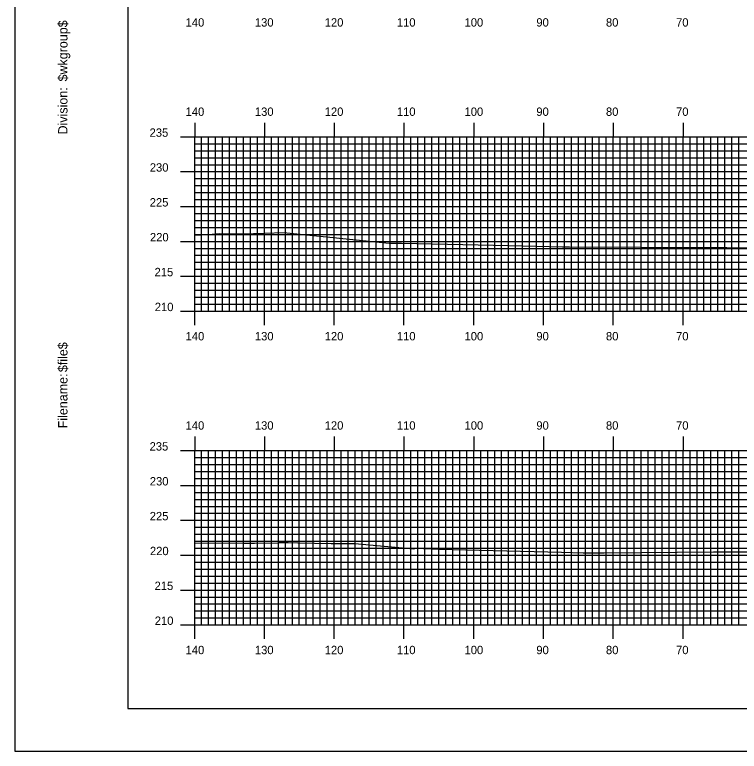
# Model space of a CAD drawing. Extents: x 1804290 to 1804634, y 442591 to 442811.
# Drawn here: x 1804290.4 to 1804394.2, y 442590.5 to 442696.2 of the extents above; entities that cross this region are included whole.
import ezdxf

# ---------------------------------------------------------------- set-up
doc = ezdxf.new("R2010")
doc.units = 0
for name, color, linetype in [('BORDER', 7, 'Continuous'), ('H_V ANNOTATION', 7, 'Continuous'), ('MAJOR', 7, 'Continuous'), ('MINOR', 7, 'Continuous'), ('PLOT BOUNDARY', 7, 'Continuous'), ('S_Roadway_Centerline', 7, 'Continuous')]:
    doc.layers.add(name, color=color, linetype=linetype)

msp = doc.modelspace()

# ---------------------------------------------------------------- linework, layer by layer
at = {"layer": 'BORDER'}
msp.add_lwpolyline([(1804306.57, 442596.67), (1804626.57, 442596.67), (1804626.57, 442806.67), (1804306.57, 442806.67)], close=True, dxfattribs=at)
at = {"layer": 'MAJOR'}
for p, q in [((1804316.17, 442680.67), (1804316.17, 442678.67)), ((1804326.17, 442680.67), (1804326.17, 442678.67)), ((1804336.17, 442680.67), (1804336.17, 442678.67)), ((1804346.17, 442680.67), (1804346.17, 442678.67)), ((1804356.17, 442680.67), (1804356.17, 442678.67)), ((1804366.17, 442680.67), (1804366.17, 442678.67)), ((1804376.17, 442680.67), (1804376.17, 442678.67)), ((1804386.17, 442680.67), (1804386.17, 442678.67)), ((1804314.16, 442678.67), (1804316.17, 442678.67)), ((1804316.17, 442678.67), (1804596.17, 442678.67)), ((1804316.17, 442653.67), (1804316.17, 442678.67)), ((1804316.17, 442653.67), (1804316.17, 442678.67)), ((1804316.17, 442678.67), (1804596.17, 442678.67)), ((1804326.17, 442653.67), (1804326.17, 442678.67)), ((1804336.17, 442653.67), (1804336.17, 442678.67)), ((1804346.17, 442653.67), (1804346.17, 442678.67)), ((1804356.17, 442653.67), (1804356.17, 442678.67)), ((1804366.17, 442653.67), (1804366.17, 442678.67)), ((1804376.17, 442653.67), (1804376.17, 442678.67)), ((1804386.17, 442653.67), (1804386.17, 442678.67)), ((1804314.16, 442673.67), (1804316.17, 442673.67)), ((1804316.17, 442673.67), (1804596.17, 442673.67)), ((1804314.16, 442668.67), (1804316.17, 442668.67)), ((1804316.17, 442668.67), (1804596.17, 442668.67)), ((1804314.16, 442663.67), (1804316.17, 442663.67)), ((1804316.17, 442663.67), (1804596.17, 442663.67)), ((1804314.16, 442658.67), (1804316.17, 442658.67)), ((1804316.17, 442658.67), (1804596.17, 442658.67)), ((1804314.16, 442653.67), (1804316.17, 442653.67)), ((1804316.17, 442653.67), (1804596.17, 442653.67)), ((1804316.17, 442653.67), (1804596.17, 442653.67)), ((1804316.17, 442651.66), (1804316.17, 442653.67)), ((1804326.17, 442651.66), (1804326.17, 442653.67)), ((1804336.17, 442651.66), (1804336.17, 442653.67)), ((1804346.17, 442651.66), (1804346.17, 442653.67)), ((1804356.17, 442651.66), (1804356.17, 442653.67)), ((1804366.17, 442651.66), (1804366.17, 442653.67)), ((1804376.17, 442651.66), (1804376.17, 442653.67)), ((1804386.17, 442651.66), (1804386.17, 442653.67)), ((1804316.17, 442635.67), (1804316.17, 442633.67)), ((1804326.17, 442635.67), (1804326.17, 442633.67)), ((1804336.17, 442635.67), (1804336.17, 442633.67)), ((1804346.17, 442635.67), (1804346.17, 442633.67)), ((1804356.17, 442635.67), (1804356.17, 442633.67)), ((1804366.17, 442635.67), (1804366.17, 442633.67)), ((1804376.17, 442635.67), (1804376.17, 442633.67)), ((1804386.17, 442635.67), (1804386.17, 442633.67)), ((1804314.16, 442633.67), (1804316.17, 442633.67)), ((1804316.17, 442633.67), (1804596.17, 442633.67)), ((1804316.17, 442608.67), (1804316.17, 442633.67)), ((1804316.17, 442608.67), (1804316.17, 442633.67)), ((1804316.17, 442633.67), (1804596.17, 442633.67)), ((1804326.17, 442608.67), (1804326.17, 442633.67)), ((1804336.17, 442608.67), (1804336.17, 442633.67)), ((1804346.17, 442608.67), (1804346.17, 442633.67)), ((1804356.17, 442608.67), (1804356.17, 442633.67)), ((1804366.17, 442608.67), (1804366.17, 442633.67)), ((1804376.17, 442608.67), (1804376.17, 442633.67)), ((1804386.17, 442608.67), (1804386.17, 442633.67)), ((1804314.16, 442628.67), (1804316.17, 442628.67)), ((1804316.17, 442628.67), (1804596.17, 442628.67)), ((1804314.16, 442623.67), (1804316.17, 442623.67)), ((1804316.17, 442623.67), (1804596.17, 442623.67)), ((1804314.16, 442618.67), (1804316.17, 442618.67)), ((1804316.17, 442618.67), (1804596.17, 442618.67)), ((1804314.16, 442613.67), (1804316.17, 442613.67)), ((1804316.17, 442613.67), (1804596.17, 442613.67)), ((1804314.16, 442608.67), (1804316.17, 442608.67)), ((1804316.17, 442608.67), (1804596.17, 442608.67)), ((1804316.17, 442608.67), (1804596.17, 442608.67)), ((1804316.17, 442606.66), (1804316.17, 442608.67)), ((1804326.17, 442606.66), (1804326.17, 442608.67)), ((1804336.17, 442606.66), (1804336.17, 442608.67)), ((1804346.17, 442606.66), (1804346.17, 442608.67)), ((1804356.17, 442606.66), (1804356.17, 442608.67)), ((1804366.17, 442606.66), (1804366.17, 442608.67)), ((1804376.17, 442606.66), (1804376.17, 442608.67)), ((1804386.17, 442606.66), (1804386.17, 442608.67))]:
    msp.add_line(p, q, dxfattribs=at)
at = {"layer": 'MINOR'}
for p, q in [((1804317.17, 442653.67), (1804317.17, 442678.67)), ((1804318.17, 442653.67), (1804318.17, 442678.67)), ((1804319.17, 442653.67), (1804319.17, 442678.67)), ((1804320.17, 442653.67), (1804320.17, 442678.67)), ((1804321.17, 442653.67), (1804321.17, 442678.67)), ((1804322.17, 442653.67), (1804322.17, 442678.67)), ((1804323.17, 442653.67), (1804323.17, 442678.67)), ((1804324.17, 442653.67), (1804324.17, 442678.67)), ((1804325.17, 442653.67), (1804325.17, 442678.67)), ((1804327.17, 442653.67), (1804327.17, 442678.67)), ((1804328.17, 442653.67), (1804328.17, 442678.67)), ((1804329.17, 442653.67), (1804329.17, 442678.67)), ((1804330.17, 442653.67), (1804330.17, 442678.67)), ((1804331.17, 442653.67), (1804331.17, 442678.67)), ((1804332.17, 442653.67), (1804332.17, 442678.67)), ((1804333.17, 442653.67), (1804333.17, 442678.67)), ((1804334.17, 442653.67), (1804334.17, 442678.67)), ((1804335.17, 442653.67), (1804335.17, 442678.67)), ((1804337.17, 442653.67), (1804337.17, 442678.67)), ((1804338.17, 442653.67), (1804338.17, 442678.67)), ((1804339.17, 442653.67), (1804339.17, 442678.67)), ((1804340.17, 442653.67), (1804340.17, 442678.67)), ((1804341.17, 442653.67), (1804341.17, 442678.67)), ((1804342.17, 442653.67), (1804342.17, 442678.67)), ((1804343.17, 442653.67), (1804343.17, 442678.67)), ((1804344.17, 442653.67), (1804344.17, 442678.67)), ((1804345.17, 442653.67), (1804345.17, 442678.67)), ((1804347.17, 442653.67), (1804347.17, 442678.67)), ((1804348.17, 442653.67), (1804348.17, 442678.67)), ((1804349.17, 442653.67), (1804349.17, 442678.67)), ((1804350.17, 442653.67), (1804350.17, 442678.67)), ((1804351.17, 442653.67), (1804351.17, 442678.67)), ((1804352.17, 442653.67), (1804352.17, 442678.67)), ((1804353.17, 442653.67), (1804353.17, 442678.67)), ((1804354.17, 442653.67), (1804354.17, 442678.67)), ((1804355.17, 442653.67), (1804355.17, 442678.67)), ((1804357.17, 442653.67), (1804357.17, 442678.67)), ((1804358.17, 442653.67), (1804358.17, 442678.67)), ((1804359.17, 442653.67), (1804359.17, 442678.67)), ((1804360.17, 442653.67), (1804360.17, 442678.67)), ((1804361.17, 442653.67), (1804361.17, 442678.67)), ((1804362.17, 442653.67), (1804362.17, 442678.67)), ((1804363.17, 442653.67), (1804363.17, 442678.67)), ((1804364.17, 442653.67), (1804364.17, 442678.67)), ((1804365.17, 442653.67), (1804365.17, 442678.67)), ((1804367.17, 442653.67), (1804367.17, 442678.67)), ((1804368.17, 442653.67), (1804368.17, 442678.67)), ((1804369.17, 442653.67), (1804369.17, 442678.67)), ((1804370.17, 442653.67), (1804370.17, 442678.67)), ((1804371.17, 442653.67), (1804371.17, 442678.67)), ((1804372.17, 442653.67), (1804372.17, 442678.67)), ((1804373.17, 442653.67), (1804373.17, 442678.67)), ((1804374.17, 442653.67), (1804374.17, 442678.67)), ((1804375.17, 442653.67), (1804375.17, 442678.67)), ((1804377.17, 442653.67), (1804377.17, 442678.67)), ((1804378.17, 442653.67), (1804378.17, 442678.67)), ((1804379.17, 442653.67), (1804379.17, 442678.67)), ((1804380.17, 442653.67), (1804380.17, 442678.67)), ((1804381.17, 442653.67), (1804381.17, 442678.67)), ((1804382.17, 442653.67), (1804382.17, 442678.67)), ((1804383.17, 442653.67), (1804383.17, 442678.67)), ((1804384.17, 442653.67), (1804384.17, 442678.67)), ((1804385.17, 442653.67), (1804385.17, 442678.67)), ((1804387.17, 442653.67), (1804387.17, 442678.67)), ((1804388.17, 442653.67), (1804388.17, 442678.67)), ((1804389.17, 442653.67), (1804389.17, 442678.67)), ((1804390.17, 442653.67), (1804390.17, 442678.67)), ((1804391.17, 442653.67), (1804391.17, 442678.67)), ((1804392.17, 442653.67), (1804392.17, 442678.67)), ((1804393.17, 442653.67), (1804393.17, 442678.67)), ((1804394.17, 442653.67), (1804394.17, 442678.67)), ((1804316.17, 442677.67), (1804596.17, 442677.67)), ((1804316.17, 442677.67), (1804318.17, 442677.67)), ((1804316.17, 442676.67), (1804596.17, 442676.67)), ((1804316.17, 442676.67), (1804318.17, 442676.67)), ((1804316.17, 442675.67), (1804596.17, 442675.67)), ((1804316.17, 442675.67), (1804318.17, 442675.67)), ((1804316.17, 442674.67), (1804596.17, 442674.67)), ((1804316.17, 442674.67), (1804318.17, 442674.67)), ((1804316.17, 442672.67), (1804596.17, 442672.67)), ((1804316.17, 442672.67), (1804318.17, 442672.67)), ((1804316.17, 442671.67), (1804596.17, 442671.67)), ((1804316.17, 442671.67), (1804318.17, 442671.67)), ((1804316.17, 442670.67), (1804596.17, 442670.67)), ((1804316.17, 442670.67), (1804318.17, 442670.67)), ((1804316.17, 442669.67), (1804596.17, 442669.67)), ((1804316.17, 442669.67), (1804318.17, 442669.67)), ((1804316.17, 442667.67), (1804596.17, 442667.67)), ((1804316.17, 442667.67), (1804318.17, 442667.67)), ((1804316.17, 442666.67), (1804596.17, 442666.67)), ((1804316.17, 442666.67), (1804318.17, 442666.67)), ((1804316.17, 442665.67), (1804596.17, 442665.67)), ((1804316.17, 442665.67), (1804318.17, 442665.67)), ((1804316.17, 442664.67), (1804596.17, 442664.67)), ((1804316.17, 442664.67), (1804318.17, 442664.67)), ((1804316.17, 442662.67), (1804596.17, 442662.67)), ((1804316.17, 442662.67), (1804318.17, 442662.67)), ((1804316.17, 442661.67), (1804596.17, 442661.67)), ((1804316.17, 442661.67), (1804318.17, 442661.67)), ((1804316.17, 442660.67), (1804596.17, 442660.67)), ((1804316.17, 442660.67), (1804318.17, 442660.67)), ((1804316.17, 442659.67), (1804596.17, 442659.67)), ((1804316.17, 442659.67), (1804318.17, 442659.67)), ((1804316.17, 442657.67), (1804596.17, 442657.67)), ((1804316.17, 442657.67), (1804318.17, 442657.67)), ((1804316.17, 442656.67), (1804596.17, 442656.67)), ((1804316.17, 442656.67), (1804318.17, 442656.67)), ((1804316.17, 442655.67), (1804596.17, 442655.67)), ((1804316.17, 442655.67), (1804318.17, 442655.67)), ((1804316.17, 442654.67), (1804596.17, 442654.67)), ((1804316.17, 442654.67), (1804318.17, 442654.67)), ((1804317.17, 442608.67), (1804317.17, 442633.67)), ((1804318.17, 442608.67), (1804318.17, 442633.67)), ((1804319.17, 442608.67), (1804319.17, 442633.67)), ((1804320.17, 442608.67), (1804320.17, 442633.67)), ((1804321.17, 442608.67), (1804321.17, 442633.67)), ((1804322.17, 442608.67), (1804322.17, 442633.67)), ((1804323.17, 442608.67), (1804323.17, 442633.67)), ((1804324.17, 442608.67), (1804324.17, 442633.67)), ((1804325.17, 442608.67), (1804325.17, 442633.67)), ((1804327.17, 442608.67), (1804327.17, 442633.67)), ((1804328.17, 442608.67), (1804328.17, 442633.67)), ((1804329.17, 442608.67), (1804329.17, 442633.67)), ((1804330.17, 442608.67), (1804330.17, 442633.67)), ((1804331.17, 442608.67), (1804331.17, 442633.67)), ((1804332.17, 442608.67), (1804332.17, 442633.67)), ((1804333.17, 442608.67), (1804333.17, 442633.67)), ((1804334.17, 442608.67), (1804334.17, 442633.67)), ((1804335.17, 442608.67), (1804335.17, 442633.67)), ((1804337.17, 442608.67), (1804337.17, 442633.67)), ((1804338.17, 442608.67), (1804338.17, 442633.67)), ((1804339.17, 442608.67), (1804339.17, 442633.67)), ((1804340.17, 442608.67), (1804340.17, 442633.67)), ((1804341.17, 442608.67), (1804341.17, 442633.67)), ((1804342.17, 442608.67), (1804342.17, 442633.67)), ((1804343.17, 442608.67), (1804343.17, 442633.67)), ((1804344.17, 442608.67), (1804344.17, 442633.67)), ((1804345.17, 442608.67), (1804345.17, 442633.67)), ((1804347.17, 442608.67), (1804347.17, 442633.67)), ((1804348.17, 442608.67), (1804348.17, 442633.67)), ((1804349.17, 442608.67), (1804349.17, 442633.67)), ((1804350.17, 442608.67), (1804350.17, 442633.67)), ((1804351.17, 442608.67), (1804351.17, 442633.67)), ((1804352.17, 442608.67), (1804352.17, 442633.67)), ((1804353.17, 442608.67), (1804353.17, 442633.67)), ((1804354.17, 442608.67), (1804354.17, 442633.67)), ((1804355.17, 442608.67), (1804355.17, 442633.67)), ((1804357.17, 442608.67), (1804357.17, 442633.67)), ((1804358.17, 442608.67), (1804358.17, 442633.67)), ((1804359.17, 442608.67), (1804359.17, 442633.67)), ((1804360.17, 442608.67), (1804360.17, 442633.67)), ((1804361.17, 442608.67), (1804361.17, 442633.67)), ((1804362.17, 442608.67), (1804362.17, 442633.67)), ((1804363.17, 442608.67), (1804363.17, 442633.67)), ((1804364.17, 442608.67), (1804364.17, 442633.67)), ((1804365.17, 442608.67), (1804365.17, 442633.67)), ((1804367.17, 442608.67), (1804367.17, 442633.67)), ((1804368.17, 442608.67), (1804368.17, 442633.67)), ((1804369.17, 442608.67), (1804369.17, 442633.67)), ((1804370.17, 442608.67), (1804370.17, 442633.67)), ((1804371.17, 442608.67), (1804371.17, 442633.67)), ((1804372.17, 442608.67), (1804372.17, 442633.67)), ((1804373.17, 442608.67), (1804373.17, 442633.67)), ((1804374.17, 442608.67), (1804374.17, 442633.67)), ((1804375.17, 442608.67), (1804375.17, 442633.67)), ((1804377.17, 442608.67), (1804377.17, 442633.67)), ((1804378.17, 442608.67), (1804378.17, 442633.67)), ((1804379.17, 442608.67), (1804379.17, 442633.67)), ((1804380.17, 442608.67), (1804380.17, 442633.67)), ((1804381.17, 442608.67), (1804381.17, 442633.67)), ((1804382.17, 442608.67), (1804382.17, 442633.67)), ((1804383.17, 442608.67), (1804383.17, 442633.67)), ((1804384.17, 442608.67), (1804384.17, 442633.67)), ((1804385.17, 442608.67), (1804385.17, 442633.67)), ((1804387.17, 442608.67), (1804387.17, 442633.67)), ((1804388.17, 442608.67), (1804388.17, 442633.67)), ((1804389.17, 442608.67), (1804389.17, 442633.67)), ((1804390.17, 442608.67), (1804390.17, 442633.67)), ((1804391.17, 442608.67), (1804391.17, 442633.67)), ((1804392.17, 442608.67), (1804392.17, 442633.67)), ((1804393.17, 442608.67), (1804393.17, 442633.67)), ((1804394.17, 442608.67), (1804394.17, 442633.67)), ((1804316.17, 442632.67), (1804596.17, 442632.67)), ((1804316.17, 442632.67), (1804318.17, 442632.67)), ((1804316.17, 442631.67), (1804596.17, 442631.67)), ((1804316.17, 442631.67), (1804318.17, 442631.67)), ((1804316.17, 442630.67), (1804596.17, 442630.67)), ((1804316.17, 442630.67), (1804318.17, 442630.67)), ((1804316.17, 442629.67), (1804596.17, 442629.67)), ((1804316.17, 442629.67), (1804318.17, 442629.67)), ((1804316.17, 442627.67), (1804596.17, 442627.67)), ((1804316.17, 442627.67), (1804318.17, 442627.67)), ((1804316.17, 442626.67), (1804596.17, 442626.67)), ((1804316.17, 442626.67), (1804318.17, 442626.67)), ((1804316.17, 442625.67), (1804596.17, 442625.67)), ((1804316.17, 442625.67), (1804318.17, 442625.67)), ((1804316.17, 442624.67), (1804596.17, 442624.67)), ((1804316.17, 442624.67), (1804318.17, 442624.67)), ((1804316.17, 442622.67), (1804596.17, 442622.67)), ((1804316.17, 442622.67), (1804318.17, 442622.67)), ((1804316.17, 442621.67), (1804596.17, 442621.67)), ((1804316.17, 442621.67), (1804318.17, 442621.67)), ((1804316.17, 442620.67), (1804596.17, 442620.67)), ((1804316.17, 442620.67), (1804318.17, 442620.67)), ((1804316.17, 442619.67), (1804596.17, 442619.67)), ((1804316.17, 442619.67), (1804318.17, 442619.67)), ((1804316.17, 442617.67), (1804596.17, 442617.67)), ((1804316.17, 442617.67), (1804318.17, 442617.67)), ((1804316.17, 442616.67), (1804596.17, 442616.67)), ((1804316.17, 442616.67), (1804318.17, 442616.67)), ((1804316.17, 442615.67), (1804596.17, 442615.67)), ((1804316.17, 442615.67), (1804318.17, 442615.67)), ((1804316.17, 442614.67), (1804596.17, 442614.67)), ((1804316.17, 442614.67), (1804318.17, 442614.67)), ((1804316.17, 442612.67), (1804596.17, 442612.67)), ((1804316.17, 442612.67), (1804318.17, 442612.67)), ((1804316.17, 442611.67), (1804596.17, 442611.67)), ((1804316.17, 442611.67), (1804318.17, 442611.67)), ((1804316.17, 442610.67), (1804596.17, 442610.67)), ((1804316.17, 442610.67), (1804318.17, 442610.67)), ((1804316.17, 442609.67), (1804596.17, 442609.67)), ((1804316.17, 442609.67), (1804318.17, 442609.67))]:
    msp.add_line(p, q, dxfattribs=at)
at = {"layer": 'PLOT BOUNDARY'}
msp.add_lwpolyline([(1804290.38, 442590.55), (1804630.38, 442590.55), (1804630.38, 442810.55), (1804290.38, 442810.55)], close=True, dxfattribs=at)
at = {"layer": 'S_Roadway_Centerline'}
for points in [[(1804316.17, 442664.54), (1804318.17, 442664.65), (1804319.76, 442664.81), (1804321.45, 442664.77), (1804323.05, 442664.77), (1804329.11, 442664.94), (1804329.37, 442664.88), (1804344.06, 442663.41), (1804345.81, 442663.39), (1804361.21, 442663.07), (1804368.9, 442662.9), (1804369.33, 442662.9), (1804369.88, 442662.89), (1804390.26, 442662.79), (1804392.45, 442662.79), (1804403.75, 442662.75)], [(1804316.17, 442620.44), (1804323.26, 442620.37), (1804324.76, 442620.4), (1804328.17, 442620.44), (1804328.25, 442620.47), (1804329.55, 442620.48), (1804330.94, 442620.45), (1804335.75, 442620.32), (1804338.44, 442620.34), (1804339.13, 442620.34), (1804347.55, 442619.59), (1804347.93, 442619.68), (1804351.1, 442619.53), (1804368.76, 442619.11), (1804371.87, 442619), (1804374.86, 442618.99), (1804390.51, 442619.15), (1804398.72, 442619.13)]]:
    msp.add_lwpolyline(points, dxfattribs=at)

# ---------------------------------------------------------------- texts
at = {"layer": 'BORDER'}
for s, p in [('$wkgroup$', (1804297.94, 442686.6)), ('Division:', (1804297.94, 442679)), ('$file$', (1804297.94, 442644.92)), ('Filename:', (1804297.94, 442636.86))]:
    msp.add_text(s, height=1.339, rotation=90, dxfattribs=at).set_placement(p)
at = {"layer": 'H_V ANNOTATION'}
for s, p in [('140', (1804314.87, 442694.47)), ('130', (1804324.8, 442694.47)), ('120', (1804334.81, 442694.47)), ('110', (1804345.15, 442694.47)), ('100', (1804354.85, 442694.47)), ('90', (1804365.14, 442694.47)), ('80', (1804375.12, 442694.47)), ('70', (1804385.17, 442694.47)), ('140', (1804314.87, 442681.67)), ('130', (1804324.8, 442681.67)), ('120', (1804334.81, 442681.67)), ('110', (1804345.15, 442681.67)), ('100', (1804354.85, 442681.67)), ('90', (1804365.14, 442681.67)), ('80', (1804375.12, 442681.67)), ('70', (1804385.17, 442681.67)), ('235', (1804309.71, 442678.67)), ('230', (1804309.74, 442673.67)), ('225', (1804309.73, 442668.67)), ('220', (1804309.76, 442663.67)), ('215', (1804310.42, 442658.67)), ('210', (1804310.45, 442653.67)), ('140', (1804314.87, 442649.47)), ('130', (1804324.8, 442649.47)), ('120', (1804334.81, 442649.47)), ('110', (1804345.15, 442649.47)), ('100', (1804354.85, 442649.47)), ('90', (1804365.14, 442649.47)), ('80', (1804375.12, 442649.47)), ('70', (1804385.17, 442649.47)), ('140', (1804314.87, 442636.67)), ('130', (1804324.8, 442636.67)), ('120', (1804334.81, 442636.67)), ('110', (1804345.15, 442636.67)), ('100', (1804354.85, 442636.67)), ('90', (1804365.14, 442636.67)), ('80', (1804375.12, 442636.67)), ('70', (1804385.17, 442636.67)), ('235', (1804309.71, 442633.67)), ('230', (1804309.74, 442628.67)), ('225', (1804309.73, 442623.67)), ('220', (1804309.76, 442618.67)), ('215', (1804310.42, 442613.67)), ('210', (1804310.45, 442608.67)), ('140', (1804314.87, 442604.47)), ('130', (1804324.8, 442604.47)), ('120', (1804334.81, 442604.47)), ('110', (1804345.15, 442604.47)), ('100', (1804354.85, 442604.47)), ('90', (1804365.14, 442604.47)), ('80', (1804375.12, 442604.47)), ('70', (1804385.17, 442604.47))]:
    msp.add_text(s, height=1.2, dxfattribs=at).set_placement(p)
at = {"layer": 'MAJOR'}
for p in [(1804316.16, 442653.67), (1804316.16, 442608.67)]:
    msp.add_text('-', height=0.012, dxfattribs=at).set_placement(p)

doc.saveas('drawing.dxf')
